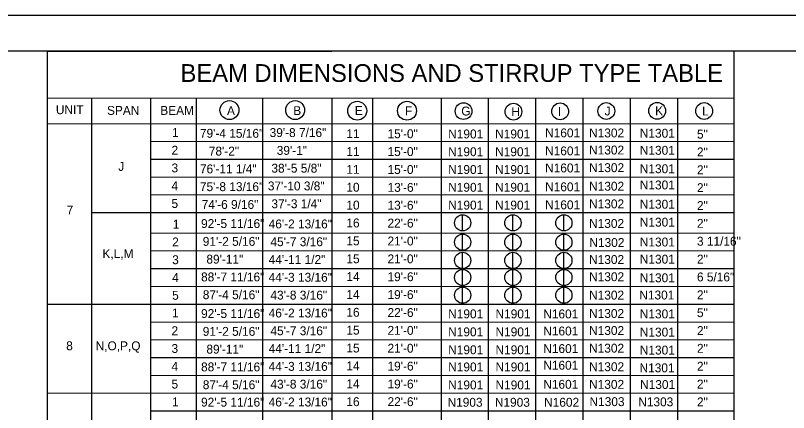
# Model space of a CAD drawing. Extents: x -50.5 to -14.4, y -5.1 to 16.9.
# Drawn here: x -36.11 to -25.23, y 11.35 to 16.93 of the extents above; entities that cross this region are included whole.
import ezdxf

# ---------------------------------------------------------------- set-up
doc = ezdxf.new("R2010")
doc.units = 0
for name, color, linetype in [('BR_AUTO DIMENSION', 7, 'Continuous'), ('BR_BORDER LINES', 7, 'Continuous'), ('BR_TABLE LINES', 7, 'Continuous'), ('BR_TEXT', 7, 'Continuous'), ('Level 31', 7, 'Continuous')]:
    doc.layers.add(name, color=color, linetype=linetype)

msp = doc.modelspace()

# ---------------------------------------------------------------- linework, layer by layer
at = {"layer": 'BR_AUTO DIMENSION'}
for p, q in [((-29.821, 13.905), (-29.821, 14.133)), ((-29.113, 13.905), (-29.113, 14.133)), ((-28.396, 13.905), (-28.396, 14.133)), ((-29.821, 13.633), (-29.821, 13.861)), ((-29.113, 13.633), (-29.113, 13.861)), ((-28.396, 13.633), (-28.396, 13.861)), ((-29.821, 13.377), (-29.821, 13.605)), ((-29.113, 13.377), (-29.113, 13.605)), ((-28.396, 13.377), (-28.396, 13.605)), ((-29.821, 13.137), (-29.821, 13.365)), ((-29.113, 13.137), (-29.113, 13.365)), ((-28.396, 13.137), (-28.396, 13.365)), ((-29.821, 12.889), (-29.821, 13.116)), ((-29.113, 12.889), (-29.113, 13.116)), ((-28.396, 12.889), (-28.396, 13.116))]:
    msp.add_line(p, q, dxfattribs=at)
for centre, radius in [((-33.103, 15.604), 0.133), ((-32.178, 15.604), 0.133), ((-31.304, 15.595), 0.133), ((-30.604, 15.595), 0.133), ((-29.821, 14.019), 0.114), ((-29.113, 14.019), 0.114), ((-28.396, 14.019), 0.114), ((-29.821, 13.747), 0.114), ((-29.113, 13.747), 0.114), ((-28.396, 13.747), 0.114), ((-29.821, 13.491), 0.114), ((-29.113, 13.491), 0.114), ((-28.396, 13.491), 0.114), ((-29.821, 13.251), 0.114), ((-29.113, 13.251), 0.114), ((-28.396, 13.251), 0.114), ((-29.821, 13.002), 0.114), ((-29.113, 13.002), 0.114), ((-28.396, 13.002), 0.114)]:
    msp.add_circle(centre, radius, dxfattribs=at)
at = {"layer": 'BR_BORDER LINES'}
for p, q in [((-15.019, 16.434), (-48.685, 16.434)), ((-35.666, 16.434), (-35.666, 6.628)), ((-35.666, 16.434), (-31.663, 16.43)), ((-26.006, 16.43), (-26.006, 6.625))]:
    msp.add_line(p, q, dxfattribs=at)
at = {"layer": 'BR_TABLE LINES'}
for p, q in [((-35.666, 15.775), (-26.006, 15.772)), ((-35.045, 15.774), (-35.045, 6.628)), ((-34.213, 15.774), (-34.213, 6.628)), ((-33.572, 15.773), (-33.572, 6.628)), ((-32.639, 15.772), (-32.639, 6.628)), ((-31.663, 15.771), (-31.663, 6.625)), ((-31.091, 15.771), (-31.091, 6.625)), ((-30.122, 15.771), (-30.122, 6.625)), ((-29.462, 15.771), (-29.462, 6.625)), ((-28.796, 15.771), (-28.796, 6.625)), ((-28.13, 15.771), (-28.13, 6.625)), ((-27.464, 15.771), (-27.464, 6.625)), ((-26.798, 15.771), (-26.798, 6.625)), ((-26.006, 15.771), (-26.006, 6.625)), ((-35.666, 15.416), (-26.006, 15.413)), ((-34.213, 15.166), (-26.006, 15.163)), ((-34.213, 14.916), (-26.006, 14.913)), ((-34.213, 14.666), (-26.006, 14.663)), ((-34.213, 14.416), (-26.006, 14.413)), ((-35.045, 14.166), (-26.006, 14.163)), ((-34.213, 13.878), (-26.006, 13.875)), ((-34.213, 13.628), (-26.006, 13.625)), ((-34.213, 13.378), (-26.006, 13.375)), ((-34.213, 13.128), (-26.006, 13.125)), ((-35.666, 12.878), (-26.006, 12.875)), ((-34.213, 12.628), (-26.006, 12.625)), ((-34.213, 12.378), (-26.006, 12.375)), ((-34.213, 12.128), (-26.006, 12.125)), ((-34.213, 11.878), (-26.006, 11.875)), ((-35.666, 11.628), (-26.006, 11.625)), ((-34.213, 11.378), (-26.006, 11.375))]:
    msp.add_line(p, q, dxfattribs=at)
at = {"layer": 'BR_TEXT'}
for centre in [(-29.808, 15.59), (-29.106, 15.582), (-28.448, 15.586), (-27.799, 15.591), (-27.083, 15.594), (-26.421, 15.591)]:
    msp.add_circle(centre, 0.118, dxfattribs=at)
at = {"layer": 'Level 31'}
msp.add_lwpolyline([(-50.519, -5.066), (-14.519, -5.066), (-14.519, 16.934), (-50.519, 16.934)], close=True, dxfattribs=at)

# ---------------------------------------------------------------- texts
at = {"layer": 'BR_TEXT'}
for s, height, p in [('BEAM DIMENSIONS AND STIRRUP TYPE TABLE', 0.25, (-33.791, 16)), ('E', 0.125, (-31.338, 15.535)), ('F', 0.125, (-30.634, 15.53)), ('1', 0.125, (-33.91, 15.228)), ('79\'-4 15/16"', 0.125, (-33.518, 15.215)), ('39\'-8 7/16"', 0.125, (-32.537, 15.225)), ('N1601', 0.125, (-28.66, 15.221)), ('N1302', 0.125, (-28.041, 15.22)), ('N1301', 0.125, (-27.327, 15.216)), ('11', 0.125, (-31.457, 15.21)), ('15\'-0"', 0.125, (-30.878, 15.209)), ('N1901', 0.125, (-30.024, 15.206)), ('N1901', 0.125, (-29.363, 15.206)), ('5"', 0.125, (-26.523, 15.204)), ('2', 0.125, (-33.918, 14.978)), ('78\'-2"', 0.125, (-33.393, 14.965)), ('39\'-1"', 0.125, (-32.437, 14.975)), ('11', 0.125, (-31.457, 14.959)), ('15\'-0"', 0.125, (-30.878, 14.958)), ('N1901', 0.125, (-30.024, 14.956)), ('N1901', 0.125, (-29.363, 14.956)), ('N1601', 0.125, (-28.66, 14.968)), ('N1302', 0.125, (-28.041, 14.98)), ('N1301', 0.125, (-27.327, 14.976)), ('2"', 0.125, (-26.523, 14.953)), ('3', 0.125, (-33.918, 14.728)), ('76\'-11 1/4"', 0.125, (-33.518, 14.715)), ('38\'-5 5/8"', 0.125, (-32.512, 14.725)), ('11', 0.125, (-31.457, 14.708)), ('15\'-0"', 0.125, (-30.878, 14.706)), ('N1901', 0.125, (-30.024, 14.706)), ('N1901', 0.125, (-29.363, 14.706)), ('N1601', 0.125, (-28.66, 14.728)), ('N1302', 0.125, (-28.041, 14.732)), ('N1301', 0.125, (-27.327, 14.717)), ('2"', 0.125, (-26.523, 14.702)), ('4', 0.125, (-33.918, 14.478)), ('75\'-8 13/16"', 0.125, (-33.518, 14.465)), ('37\'-10 3/8"', 0.125, (-32.562, 14.475)), ('10', 0.125, (-31.457, 14.457)), ('13\'-6"', 0.125, (-30.878, 14.455)), ('N1901', 0.125, (-30.024, 14.456)), ('N1901', 0.125, (-29.363, 14.456)), ('N1601', 0.125, (-28.66, 14.463)), ('N1302', 0.125, (-28.041, 14.471)), ('N1301', 0.125, (-27.327, 14.489)), ('2"', 0.125, (-26.523, 14.451)), ('5', 0.125, (-33.918, 14.228)), ('74\'-6 9/16"', 0.125, (-33.493, 14.215)), ('37\'-3 1/4"', 0.125, (-32.512, 14.225)), ('10', 0.125, (-31.457, 14.206)), ('13\'-6"', 0.125, (-30.878, 14.204)), ('N1901', 0.125, (-30.024, 14.206)), ('N1901', 0.125, (-29.363, 14.206)), ('N1601', 0.125, (-28.66, 14.21)), ('N1302', 0.125, (-28.041, 14.223)), ('N1301', 0.125, (-27.327, 14.218)), ('2"', 0.125, (-26.523, 14.2)), ('1', 0.125, (-33.9, 13.938)), ('92\'-5 11/16"', 0.125, (-33.502, 13.946)), ('46\'-2 13/16"', 0.125, (-32.551, 13.941)), ('16', 0.125, (-31.457, 13.955)), ('22\'-6"', 0.125, (-30.878, 13.953)), ('N1302', 0.125, (-28.041, 13.948)), ('N1301', 0.125, (-27.327, 13.966)), ('2"', 0.125, (-26.523, 13.949)), ('91\'-2 5/16"', 0.125, (-33.478, 13.696)), ('45\'-7 3/16"', 0.125, (-32.526, 13.691)), ('15', 0.125, (-31.457, 13.703)), ('21\'-0"', 0.125, (-30.878, 13.701)), ('3 11/16"', 0.125, (-26.523, 13.698)), ('2', 0.125, (-33.909, 13.688)), ('N1302', 0.125, (-28.037, 13.68)), ('N1301', 0.125, (-27.327, 13.687)), ('3', 0.125, (-33.909, 13.438)), ('89\'-11"', 0.125, (-33.427, 13.446)), ('44\'-11 1/2"', 0.125, (-32.551, 13.441)), ('15', 0.125, (-31.457, 13.452)), ('21\'-0"', 0.125, (-30.878, 13.45)), ('N1302', 0.125, (-28.041, 13.441)), ('N1301', 0.125, (-27.327, 13.446)), ('2"', 0.125, (-26.523, 13.447)), ('4', 0.125, (-33.909, 13.188)), ('88\'-7 11/16"', 0.125, (-33.502, 13.196)), ('44\'-3 13/16"', 0.125, (-32.551, 13.191)), ('14', 0.125, (-31.457, 13.201)), ('19\'-6"', 0.125, (-30.878, 13.199)), ('N1302', 0.125, (-28.041, 13.199)), ('N1301', 0.125, (-27.327, 13.184)), ('6 5/16"', 0.125, (-26.523, 13.196)), ('5', 0.125, (-33.909, 12.938)), ('87\'-4 5/16"', 0.125, (-33.478, 12.946)), ('43\'-8 3/16"', 0.125, (-32.526, 12.941)), ('14', 0.125, (-31.457, 12.95)), ('19\'-6"', 0.125, (-30.878, 12.948)), ('N1302', 0.125, (-28.041, 12.941)), ('N1301', 0.125, (-27.334, 12.942)), ('2"', 0.125, (-26.523, 12.945)), ('1', 0.125, (-33.91, 12.69)), ('92\'-5 11/16"', 0.125, (-33.502, 12.681)), ('46\'-2 13/16"', 0.125, (-32.551, 12.689)), ('16', 0.125, (-31.457, 12.699)), ('22\'-6"', 0.125, (-30.878, 12.696)), ('N1901', 0.125, (-30.024, 12.677)), ('N1901', 0.125, (-29.358, 12.677)), ('N1601', 0.125, (-28.686, 12.676)), ('N1302', 0.125, (-28.041, 12.683)), ('N1301', 0.125, (-27.327, 12.676)), ('5"', 0.125, (-26.523, 12.694)), ('2', 0.125, (-33.918, 12.44)), ('91\'-2 5/16"', 0.125, (-33.478, 12.431)), ('45\'-7 3/16"', 0.125, (-32.526, 12.439)), ('15', 0.125, (-31.457, 12.448)), ('21\'-0"', 0.125, (-30.878, 12.445)), ('N1901', 0.125, (-30.024, 12.424)), ('N1901', 0.125, (-29.358, 12.424)), ('N1601', 0.125, (-28.686, 12.436)), ('N1302', 0.125, (-28.041, 12.443)), ('N1301', 0.125, (-27.327, 12.421)), ('2"', 0.125, (-26.523, 12.443)), ('3', 0.125, (-33.918, 12.19)), ('89\'-11"', 0.125, (-33.427, 12.181)), ('44\'-11 1/2"', 0.125, (-32.551, 12.189)), ('15', 0.125, (-31.457, 12.197)), ('21\'-0"', 0.125, (-30.878, 12.194)), ('N1901', 0.125, (-30.024, 12.172)), ('N1901', 0.125, (-29.358, 12.172)), ('N1601', 0.125, (-28.686, 12.189)), ('N1302', 0.125, (-28.041, 12.195)), ('N1301', 0.125, (-27.327, 12.168)), ('2"', 0.125, (-26.523, 12.192)), ('N1601', 0.125, (-28.686, 11.955)), ('4', 0.125, (-33.918, 11.94)), ('88\'-7 11/16"', 0.125, (-33.502, 11.931)), ('44\'-3 13/16"', 0.125, (-32.551, 11.939)), ('14', 0.125, (-31.457, 11.946)), ('19\'-6"', 0.125, (-30.878, 11.943)), ('N1901', 0.125, (-30.024, 11.931)), ('N1901', 0.125, (-29.358, 11.931)), ('N1302', 0.125, (-28.041, 11.934)), ('N1301', 0.125, (-27.331, 11.918)), ('2"', 0.125, (-26.523, 11.941)), ('5', 0.125, (-33.918, 11.69)), ('87\'-4 5/16"', 0.125, (-33.478, 11.681)), ('43\'-8 3/16"', 0.125, (-32.526, 11.689)), ('14', 0.125, (-31.457, 11.694)), ('19\'-6"', 0.125, (-30.878, 11.691)), ('N1901', 0.125, (-30.024, 11.678)), ('N1901', 0.125, (-29.358, 11.678)), ('N1601', 0.125, (-28.686, 11.687)), ('N1302', 0.125, (-28.041, 11.686)), ('N1301', 0.125, (-27.323, 11.684)), ('2"', 0.125, (-26.523, 11.69)), ('1', 0.125, (-33.91, 11.44)), ('92\'-5 11/16"', 0.125, (-33.502, 11.436)), ('46\'-2 13/16"', 0.125, (-32.551, 11.438)), ('16', 0.125, (-31.457, 11.443)), ('22\'-6"', 0.125, (-30.878, 11.443)), ('N1903', 0.125, (-30.033, 11.434)), ('N1903', 0.125, (-29.367, 11.434)), ('N1602', 0.125, (-28.674, 11.434)), ('N1303', 0.125, (-28.035, 11.443)), ('N1303', 0.125, (-27.349, 11.44)), ('2"', 0.125, (-26.523, 11.439))]:
    msp.add_text(s, height=height, dxfattribs=at).set_placement(p)
for s, p in [('UNIT', (-35.545, 15.547)), ('SPAN', (-34.826, 15.537)), ('BEAM', (-34.076, 15.537)), ('A', (-33.137, 15.534)), ('B', (-32.204, 15.534)), ('G', (-29.84, 15.528)), ('H', (-29.135, 15.519)), ('I', (-28.481, 15.523)), ('J', (-27.823, 15.529)), ('K', (-27.112, 15.531)), ('L', (-26.45, 15.528)), ('J', (-34.668, 14.75)), ('7', (-35.393, 14.137)), ('K,L,M', (-34.89, 13.523)), ('8', (-35.4, 12.229)), ('N,O,P,Q', (-34.986, 12.228))]:
    msp.add_text(s, height=0.125, rotation=360, dxfattribs=at).set_placement(p)

doc.saveas('drawing.dxf')
